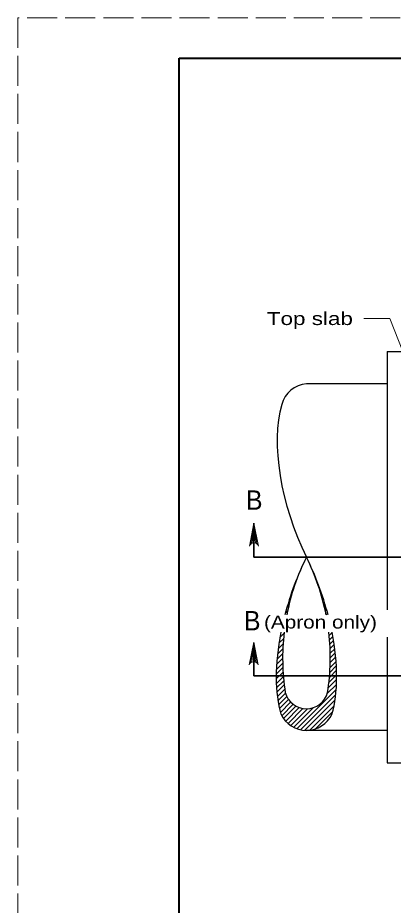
# Model space of a CAD drawing. Extents: x 1073.4 to 1107.4, y 719.4 to 741.4.
# Drawn here: x 1073.36 to 1078.01, y 730.35 to 741.35 of the extents above; entities that cross this region are included whole.
import ezdxf

# ---------------------------------------------------------------- set-up
doc = ezdxf.new("R2010")
doc.units = 0
doc.header["$LTSCALE"] = 0.062
doc.linetypes.add('LONG_DASHED', pattern=[7.5, 6, -1.5])
doc.layers.add('1', color=7, linetype='Continuous', lineweight=13)

msp = doc.modelspace()

# ---------------------------------------------------------------- linework, layer by layer
at = {"layer": '1', "lineweight": 25}
for p, q in [((1075.36142, 740.85408), (1106.86142, 740.85408)), ((1075.36142, 720.04675), (1075.36142, 740.85408)), ((1077.93667, 737.21758), (1081.73483, 737.21758)), ((1077.93667, 737.21758), (1077.93667, 734.01458)), ((1077.93667, 736.81783), (1076.93708, 736.81783)), ((1077.93667, 733.67875), (1077.93667, 732.1205)), ((1077.93667, 732.52033), (1076.93708, 732.52033)), ((1077.93667, 732.1205), (1082.93425, 732.1205))]:
    msp.add_line(p, q, dxfattribs=at)
at = {"layer": '1'}
for p, q in [((1077.97142, 737.6265), (1077.64967, 737.6265)), ((1078.12867, 737.21908), (1077.97142, 737.6265)), ((1076.24767, 734.83025), (1076.28733, 735.08967)), ((1076.26433, 734.84008), (1076.28733, 735.08967)), ((1076.3055, 734.84192), (1076.28733, 735.08967)), ((1076.32325, 734.83325), (1076.28733, 735.08967)), ((1076.55292, 734.66908), (1076.63292, 734.66908)), ((1076.76992, 734.27625), (1076.78008, 734.28642)), ((1077.08267, 734.32), (1077.08658, 734.32392)), ((1077.097, 734.27625), (1077.10217, 734.28142)), ((1076.72192, 734.13392), (1076.73992, 734.15192)), ((1077.111, 734.23192), (1077.11733, 734.23833)), ((1077.12417, 734.18692), (1077.13217, 734.19483)), ((1077.13683, 734.14133), (1077.14658, 734.15108)), ((1076.69667, 734.05058), (1076.71992, 734.07383)), ((1077.14875, 734.095), (1077.16042, 734.10667)), ((1077.16, 734.04808), (1077.17392, 734.06192)), ((1076.67417, 733.96983), (1076.70283, 733.9985)), ((1077.17067, 734.00042), (1077.18692, 734.01667)), ((1077.18117, 733.95275), (1077.19942, 733.97092)), ((1076.608, 733.67075), (1076.6585, 733.72125)), ((1077.21783, 733.69817), (1077.254, 733.73442)), ((1076.24425, 733.35675), (1076.28383, 733.61608)), ((1076.26083, 733.3665), (1076.28383, 733.61608)), ((1076.28383, 733.37108), (1076.28383, 733.61608)), ((1076.302, 733.36842), (1076.28383, 733.61608)), ((1076.31967, 733.35975), (1076.28383, 733.61608)), ((1076.58683, 733.53308), (1076.64758, 733.59383)), ((1076.59658, 733.60108), (1076.65225, 733.65675)), ((1077.22267, 733.64475), (1077.26325, 733.68542)), ((1077.22658, 733.59042), (1077.27183, 733.63575)), ((1076.57892, 733.467), (1076.64433, 733.53242)), ((1077.22942, 733.53508), (1077.27967, 733.58542)), ((1077.23125, 733.47867), (1077.28683, 733.53425)), ((1077.23183, 733.42108), (1077.29325, 733.48242)), ((1076.56783, 733.33942), (1076.642, 733.41358)), ((1076.57258, 733.40242), (1076.64258, 733.47242)), ((1077.22958, 733.30225), (1077.30342, 733.37617)), ((1077.23133, 733.36233), (1077.29883, 733.42975)), ((1076.563, 733.21808), (1076.6445, 733.29958)), ((1076.56467, 733.278), (1076.64267, 733.35608)), ((1077.22167, 733.17783), (1077.30967, 733.26592)), ((1077.22633, 733.24083), (1077.30708, 733.32158)), ((1076.56275, 733.15967), (1076.64733, 733.24425)), ((1076.56408, 733.10275), (1076.65133, 733.18992)), ((1077.20733, 733.04708), (1077.311, 733.15075)), ((1077.21533, 733.11342), (1077.311, 733.20908)), ((1076.56683, 733.04725), (1076.65617, 733.13658)), ((1076.571, 732.99325), (1076.66192, 733.08408)), ((1077.19508, 732.97667), (1077.30933, 733.09083)), ((1076.57667, 732.94067), (1076.6685, 733.0325)), ((1076.58375, 732.8895), (1076.67692, 732.98267)), ((1076.59233, 732.83983), (1076.69325, 732.94075)), ((1076.81925, 732.54267), (1077.30583, 733.02917)), ((1076.86408, 732.52925), (1077.3, 732.96508)), ((1076.60242, 732.79175), (1076.71492, 732.90417)), ((1076.61408, 732.74508), (1076.74125, 732.87225)), ((1076.63083, 732.70358), (1076.772, 732.84475)), ((1076.65358, 732.66808), (1076.80733, 732.82175)), ((1076.91467, 732.5215), (1077.29142, 732.89833)), ((1076.97275, 732.52142), (1077.27908, 732.82775)), ((1076.67975, 732.63608), (1076.84767, 732.804)), ((1076.70933, 732.60742), (1076.89417, 732.79225)), ((1076.74233, 732.58217), (1076.94933, 732.78908)), ((1076.77883, 732.56042), (1077.02042, 732.802)), ((1077.05083, 732.54125), (1077.26167, 732.75208))]:
    msp.add_line(p, q, dxfattribs=at)
at = {"layer": '1', "lineweight": 35}
for p, q in [((1076.28733, 734.84458), (1076.28733, 735.08967)), ((1076.28733, 734.66908), (1076.28733, 735.05633)), ((1076.28733, 734.66908), (1078.98608, 734.66908)), ((1076.28383, 733.19558), (1076.28383, 733.58283)), ((1076.28383, 733.19558), (1076.319, 733.19558)), ((1076.319, 733.19558), (1083.54592, 733.19558))]:
    msp.add_line(p, q, dxfattribs=at)
at = {"layer": '1', "linetype": 'LONG_DASHED'}
msp.add_lwpolyline([(1073.36142, 719.35408), (1107.36142, 719.35408), (1107.36142, 741.35408), (1073.36142, 741.35408)], close=True, dxfattribs=at)
at = {"layer": '1', "lineweight": 25}
msp.add_lwpolyline([(1106.86142, 719.85408), (1075.36142, 719.85408), (1075.36142, 740.85408)], dxfattribs=at)
at = {"layer": '1', "lineweight": 40}
msp.add_lwpolyline([(1075.36142, 740.85408), (1106.86142, 740.85408), (1106.86142, 719.85408), (1075.36142, 719.85408)], close=True, dxfattribs=at)
msp.add_lwpolyline([(1075.36142, 740.85408), (1106.86142, 740.85408), (1106.86142, 719.85408), (1075.36142, 719.85408)], close=True, dxfattribs=at)
at = {"layer": '1'}
for points in [[(1076.23075, 734.80642), (1076.28733, 735.08967), (1076.344, 734.80642)], [(1076.22725, 733.33292), (1076.28383, 733.61608), (1076.3405, 733.33292)]]:
    msp.add_lwpolyline(points, dxfattribs=at)
for centre in [(1076.28744, 734.78356), (1076.28391, 733.31006)]:
    msp.add_arc(centre, 0.06112, 22.08782, 157.91395, dxfattribs=at)
at = {"layer": '1', "lineweight": 25}
for centre, major_axis, ratio, start_param, end_param in [((1076.97186, 736.4649), (-0.35468, 0), 0.999895, 4.81061039, 6.01217703), ((1077.47912, 735.35341), (0.54382, -1.59349), 0.454236, 3.7132848, 4.99688943), ((1077.49531, 733.96414), (0.56019, 1.64146), 0.454236, 1.28629588, 1.73146945), ((1079.44544, 733.41751), (-2.80345, 0), 0.999895, 5.82035133, 6.0910741), ((1074.42844, 733.41751), (2.80345, 0), 0.999895, 0.1921112, 0.46283397), ((1076.37857, 733.96414), (-0.56019, 1.64146), 0.454236, 4.55171586, 4.99688943), ((1077.49531, 733.96414), (0.56019, 1.64146), 0.454236, 1.86183071, 2.56990051), ((1079.44544, 733.41751), (-2.80345, 0), 0.999895, 6.16899879, 6.43603853), ((1074.42844, 733.41751), (2.80345, 0), 0.999895, 6.13033209, 6.39737183), ((1076.37857, 733.96414), (-0.56019, 1.64146), 0.454236, 3.7132848, 4.4213546), ((1076.93694, 733.06014), (-0.27133, 0), 0.999895, 0.25882515, 2.88276755), ((1076.94378, 732.87908), (-0.35882, 0), 0.999895, 0.44393826, 1.55172211), ((1076.9301, 732.87908), (0.35882, 0), 0.999895, 4.7314632, 5.83924704)]:
    msp.add_ellipse(centre, major_axis=major_axis, ratio=ratio, start_param=start_param, end_param=end_param, dxfattribs=at)

# ---------------------------------------------------------------- texts
at = {"layer": '1'}
for s, height, width, p in [('Top slab', 0.16, 1.3, (1076.44583, 737.54558)), ('B', 0.24, 0.95, (1076.18933, 735.25625)), ('B', 0.24, 0.95, (1076.16467, 733.76108)), ('(Apron only)', 0.16, 1.2, (1076.41142, 733.78375))]:
    msp.add_text(s, height=height, dxfattribs=dict(at, width=width)).set_placement(p)

doc.saveas('drawing.dxf')
